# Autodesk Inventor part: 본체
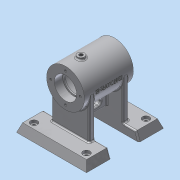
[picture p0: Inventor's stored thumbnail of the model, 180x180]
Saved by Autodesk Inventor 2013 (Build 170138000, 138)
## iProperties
Created: 2016-07
Part Number: 본체
Material: 알루미늄 6061
Document SubType Name: Modeling
Designer: dgall
Density: 2.71 g/cm^3
Mass: 502.064 g
Surface Area: 544.577 cm^2
Volume: 185.264 cm^3
Author: dgall
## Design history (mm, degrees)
sketch "스케치1"
  geometry: L1 (0, 0)-(100, 0); L2 (100, 0)-(100, 110); L3 (100, 110)-(0, 110); L4 (0, 110)-(0, 0)
  constraints: 8 end point, 2 parallel, 1 horizontal, 1 perpendicular
  dimensions: "d0" = 100 distance of L2.end L3.end; "d2" = 110 distance of L1.end L2.end
extrude "돌출1" new body sketch "스케치1" distance "d3" = 12; taper "d4" = -20 deg
sketch "스케치2"
  geometry: L1 (75, 19.882)-(35, 19.882); L2 (35, 19.882)-(35, -12.264); L3 (35, -12.264)-(75, -12.264); L4 (75, -12.264)-(75, 19.882); L5 (110, 0)-(105.632, 12) reference; 1 further point
  constraints: 8 end point, 2 parallel, 1 horizontal, 1 perpendicular
  dimensions: "d5" = 35 distance from line of point (0, 0) L2; "d6" = 35 distance from line of L4 L5.start
extrude "돌출2" cut sketch "스케치2" stored distance "d7" = 12; taper "d8" = 0 deg
node "작업 평면1"
node "작업 평면2"
sketch "스케치4"
  geometry: L1 (20, 70)-(90, 70); L2 (90, 70)-(90, 97); L3 (90, 97)-(20, 97); L4 (20, 97)-(20, 70); L5 (20, 86)-(32, 86); L6 (32, 86)-(32, 84); L7 (32, 84)-(34, 84); L8 (34, 84)-(34, 92); L9 (34, 92)-(76, 92); L10 (76, 92)-(76, 84); L11 (76, 84)-(78, 84); L12 (78, 84)-(78, 86); L13 (78, 86)-(90, 86); L14 (35, 0)-(0, 0) reference; L15 (75, 0)-(75, 12) reference; L16 (35, 0)-(75, 0); 2 further points
  constraints: 28 end point, 8 parallel, 4 perpendicular, 2 collinear, 2 horizontal alignment, 2 midpoint, 2 point on line, 1 horizontal, 1 vertical alignment
  dimensions: "d11" = 54 diameter of L3 L1; "d13" = 32 diameter of L5 L1; "d14" = 28 diameter of L7 L1; "d15" = 44 diameter of L9 L1; "d16" = 12 distance of L5.start L5.end; "d17" = 42 distance of L8.end L9.end; "d18" = 12 distance of L12.end L13.end; "d19" = 70 distance between parallel lines of L14 L1; "d20" = 70 distance of L1.start L1.end
revolve "회전1" sketch "스케치4" stored, may be unused: angle "d21" = 90 deg
node "작업 평면3"
sketch "스케치5"
  geometry: L1 (-45.632, -58)-(45.632, -58) reference; L2 (-27, 0)-(-27, -58); L3 (27, 0)-(27, -58); L4 (-27, -58)-(27, -58); A1 r 27 centre (0, 0) between (-27, 0) and (27, 0) reference; 2 further points
  constraints: 6 end point, 2 perpendicular, 2 point on circle, 2 point on line, 2 tangent, 1 coincident, 1 collinear, 1 horizontal alignment, 2 other
extrude "돌출3" join sketch "스케치5" stored distance "d23" = 56; taper "d24" = 0 deg
extrude "돌출4" cut sketch "스케치5" stored distance "d25" = 40; taper "d26" = 0 deg
node "작업 평면4"
sketch "스케치6"
  geometry: L1 (35, 70)-(35, 12) reference; L2 (20, 43)-(90, 43) reference; L3 (75, 12)-(75, 70) reference; L4 (35, 22)-(75, 22); 1 further point
  constraints: 2 end point, 2 point on line, 1 perpendicular
  dimensions: "d28" = 21 distance between parallel lines of L4 L2
feature "리브1" sketch "스케치6" dims "d29" = 1, "d30" = 8, "d31" = 0, "d32" = 0, "d33" = 1, "d34" = 1
sketch "스케치7"
  geometry: L1 (21.298, 40)-(21.298, 0) reference; L2 (7.798, 12)-(7.798, 28); L3 (14.798, 12)-(14.798, 28); L4 (11.298, 12)-(11.298, 28); L5 (43.298, -35)-(43.298, 0) reference; A1 r 3.5 centre (11.298, 12) between (7.798, 12) and (14.798, 12); A2 r 3.5 centre (11.298, 28) between (14.798, 28) and (7.798, 28); 2 further points
  constraints: 6 end point, 4 point on circle, 2 centre point, 2 midpoint, 2 tangent, 2 vertical alignment, 1 equal radius, 1 horizontal alignment, 1 parallel
  dimensions: "d35" = 3.5 radius of A1; "d37" = 23 dimension on A2 A1; "d38" = 32 distance from line of point (11.298, 20) L5
extrude "돌출5" cut sketch "스케치7" distance "d39" = 40; taper "d40" = 0 deg
node "작업 평면5"
sketch "스케치8"
  geometry: L1 (-5, 26.533)-(-5, 30); L2 (-5, 30)-(0, 30); L3 (0, 30)-(0, 27); L4 (50, -70)-(-50, -70) reference; A1 r 27 centre (0, 0) between (-5, 26.533) and (0, 27) reference; A2 r 27 centre (0, 0) between (0, 27) and (-5, 26.533)
  constraints: 6 end point, 4 point on circle, 1 centre point, 1 coincident, 1 parallel, 1 perpendicular, 1 vertical, 1 vertical alignment
  dimensions: "d42" = 5 distance of L1.end L2.end; "d44" = 100 distance between parallel lines of L4 L2
revolve "회전2" sketch "스케치8" stored, may be unused: angle "d45" = 90 deg
sketch "스케치9"
  geometry: C1 r 5 at (0, 0) reference; 1 further point
hole "구멍1" sketch "스케치9" at (0, 0) diameter "d46" = 5.188; stored, may be unused: countersink angle "d50" = 90 deg, drill point angle "d52" = 0 deg; dims "d47" = 6, "d48" = 4, "d49" = 2, "d51" = 20
node "작업 평면6"
sketch "스케치10"
  geometry: L1 (-14.308, -22.897)-(-15.898, -25.441); L2 (-15.898, -25.441)-(-20.986, -22.262); L3 (-20.986, -22.262)-(-19.038, -19.145); L4 (0, 0)-(0, -27); C1 r 16 at (0, 0) reference; A1 r 27 centre (0, 0) between (-19.038, -19.145) and (0, -27) reference; A2 r 27 centre (0, 0) between (-19.038, -19.145) and (-14.308, -22.897); 1 further point
  constraints: 8 end point, 4 point on circle, 1 centre point, 1 coincident, 1 parallel, 1 perpendicular, 1 vertical
  dimensions: "d56" = 32 deg angle of L4 L1; "d57" = 6 distance of L1.end L2.end; "d58" = 30 distance from line of C1.centre L2; "d59" = 2.54414 vertical distance of L1.start L1.end
revolve "회전3" sketch "스케치10" stored, may be unused: angle "d60" = 90 deg
sketch "스케치11"
  geometry: C1 r 6 at (0, 0) reference; 1 further point
hole "구멍2" sketch "스케치11" at (0, 0) diameter "d61" = 5.188; stored, may be unused: countersink angle "d65" = 90 deg, drill point angle "d67" = 0 deg; dims "d62" = 6, "d63" = 4, "d64" = 2, "d66" = 20
fillet "모깎기1" dims "d68" = 0.3
fillet "모깎기2" dims "d69" = 3
sketch "스케치12"
  geometry: L1 (77, 35)-(77, 27) reference; L2 (77, 27)-(23, 27) reference; L3 (23, 27)-(23, 35) reference; L4 (23, 35)-(77, 35) reference; L5 (95.632, 35)-(4.368, 35) reference; L6 (4.368, 4.368)-(4.368, 35) reference; L7 (95.632, 4.368)-(4.368, 4.368) reference; L8 (95.632, 35)-(95.632, 4.368) reference; L9 (100, 0)-(100, 35) reference; 1 further point
fillet "모깎기3" dims "d70" = 2
fillet "모깎기4" dims "d71" = 2
fillet "모깎기5" dims "d72" = 2
sketch "스케치13"
  geometry: C1 r 16 at (0, 0) reference; A1 r 21 centre (0, 0) between (0, 21) and (-21, 0); 3 further points
  constraints: 4 point on circle, 1 centre point, 1 coincident
  dimensions: "d73" = 42 diameter of A1
hole "구멍3" sketch "스케치13" at (0, 21), (-21, 0), (0, -21), (21, 0) diameter "d74" = 3.242; stored, may be unused: countersink angle "d78" = 90 deg, drill point angle "d80" = 118 deg; dims "d75" = 8, "d76" = 4, "d77" = 2, "d79" = 10
node "작업 평면7"
sketch "스케치14"
  geometry: 1 further point
sketch "스케치15"
  geometry: L1 (0, 0)-(100, 0) reference; L2 (0, 35)-(0, 0) reference; L3 (100, 0)-(100, 35) reference; 2 further points
  dimensions: "d87" = 12.5 distance from line of L2 point (12.5, 12.5); "d88" = 12.5 distance from line of point (12.5, 12.5) L1; "d89" = 12.5 distance from line of L3 point (87.5, 12.5); "d90" = 12.5 distance from line of L1 point (87.5, 12.5)
hole "구멍4" sketch "스케치15" at (12.5, 12.5), (87.5, 12.5) diameter "d91" = 6; stored, may be unused: countersink angle "d95" = 90 deg, drill point angle "d97" = 118 deg; dims "d92" = 8, "d93" = 10, "d94" = 4, "d96" = 10
node "작업 평면8"
fillet "모깎기6" dims "d99" = 2
node "작업 평면9"
sketch "스케치16"
  geometry: L1 (-35, -27)-(-35, 27) reference; L2 (-35, 27)-(35, 27) reference; 2 further points
  constraints: 1 other
  dimensions: "d100" = 35 distance from line of L1 point (0, 0); "d101" = 27 distance from line of point (0, 0) L2
feature "엠보싱1" sketch "스케치16" dims "d11" = 54, "d13" = 32, "d14" = 28, "d15" = 44, "d16" = 12, "d17" = 42, "d18" = 12, "d19" = 70, "d20" = 70, "d102" = 0.5, "d103" = 0
node "솔리드1"
mirror "대칭1"
mirror "대칭2"
node "투영된 루프1"
other parameters: "d9" = 55, "d22" = -35, "d41" = -22, "d53" = -35, "d81" = 55, "d98" = -35
